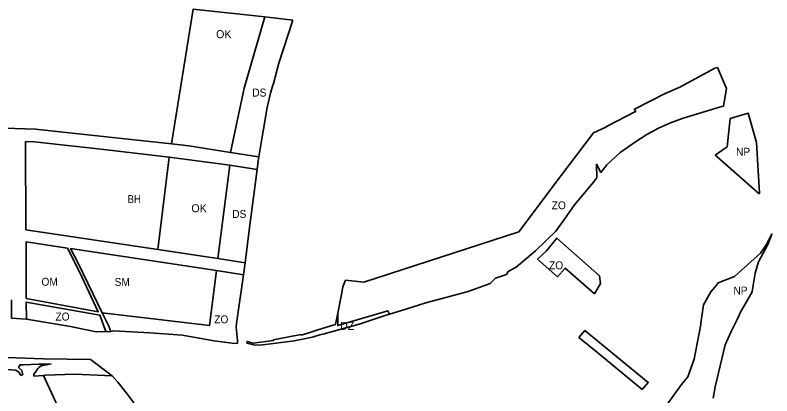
# Model space of a CAD drawing. Extents: x -650971 to -642489, y -1074311 to -1062745.
# Drawn here: x -647077 to -645942, y -1069933 to -1069362 of the extents above; entities that cross this region are included whole.
import ezdxf

# ---------------------------------------------------------------- set-up
doc = ezdxf.new("R2010")
doc.units = 0
doc.header["$LTSCALE"] = 4.8
for name, color, linetype, lineweight in [('1', 7, 'Continuous', 35), ('12', 7, 'Continuous', 35), ('13', 7, 'Continuous', 35), ('15', 7, 'Continuous', 35), ('18', 7, 'Continuous', 35), ('24', 7, 'Continuous', 35), ('25', 7, 'Continuous', 35), ('42', 7, 'Continuous', 35), ('48', 7, 'Continuous', 35), ('62', 7, 'Continuous', 35)]:
    doc.layers.add(name, color=color, linetype=linetype, lineweight=lineweight)

msp = doc.modelspace()

# ---------------------------------------------------------------- linework, layer by layer
at = {"layer": '1'}
msp.add_lwpolyline([(-646862.955, -1069713.633), (-647060.7, -1069683.894), (-647061.304, -1069551.773), (-647047.702, -1069552.239), (-646944.167, -1069563.743), (-646846, -1069575)], close=True, dxfattribs=at)
at = {"layer": '12'}
msp.add_lwpolyline([(-646998.56, -1069711.443), (-646980.4, -1069746.98), (-646952.56, -1069807.13), (-647060.23, -1069786.932), (-647060.617, -1069702.116)], close=True, dxfattribs=at)
at = {"layer": '13'}
for points in [[(-646842.441, -1069555.283), (-646809.879, -1069353.002), (-646702.425, -1069364.771)], [(-646702.425, -1069364.771), (-646733.74, -1069471.688), (-646754.066, -1069567.993)], [(-646754.066, -1069567.993), (-646816.615, -1069558.064), (-646842.441, -1069555.283)]]:
    msp.add_lwpolyline(points, dxfattribs=at)
msp.add_lwpolyline([(-646862.955, -1069713.633), (-646846, -1069575), (-646755.269, -1069587.04), (-646772.907, -1069727.176)], close=True, dxfattribs=at)
at = {"layer": '15'}
for points in [[(-647608.81, -1069551.868), (-647567.252, -1069548.083), (-647434.969, -1069537.141), (-647341.697, -1069532.602), (-647204.293, -1069530.647), (-647140.008, -1069530.068), (-647046.325, -1069533.275), (-646986.633, -1069539.757), (-646842.441, -1069555.283)], [(-646846, -1069575), (-646944.167, -1069563.743), (-647047.702, -1069552.239), (-647061.304, -1069551.773), (-647060.7, -1069683.894), (-646862.955, -1069713.633), (-646772.907, -1069727.176), (-646732.143, -1069733.308), (-646734.48, -1069751.35), (-646775.286, -1069745.022)], [(-646842.441, -1069555.283), (-646816.615, -1069558.064), (-646754.066, -1069567.993), (-646711.442, -1069574.759)], [(-646711.442, -1069574.759), (-646712.34, -1069580.49), (-646714.037, -1069593.585), (-646755.269, -1069587.04), (-646846, -1069575)], [(-646775.286, -1069745.022), (-646993.771, -1069712.163), (-646981.92, -1069734.86), (-646946.369, -1069808.291)], [(-647060.029, -1069817.854), (-647074.72, -1069816.8), (-647082.145, -1069816.321), (-647082.206, -1069802.916), (-647082.271, -1069788.81)], [(-646940.94, -1069836.34), (-646950.08, -1069812.16), (-647060.206, -1069792.294), (-647060.029, -1069817.854)], [(-646946.369, -1069808.291), (-646936.6, -1069828.47), (-646933.39, -1069836.51)], [(-646933.39, -1069836.51), (-646936.08, -1069837.11), (-646940.94, -1069836.34)], [(-646231.73, -1069845.42), (-646222.694, -1069834.722), (-646127.84, -1069912.695), (-646136.88, -1069923.39)], [(-646136.88, -1069923.39), (-646142.68, -1069918.62), (-646203.48, -1069868.65), (-646231.73, -1069845.42)], [(-647173.23, -1069871.09), (-647136.94, -1069872.55), (-647133.58, -1069872.73), (-647118.77, -1069873.51), (-647116.31, -1069873.65), (-647094.24, -1069874.85), (-647088.93, -1069875.14), (-647088.94, -1069875.34), (-647081.26, -1069875.76), (-647081.25, -1069875.56), (-647076, -1069875.85), (-647034.195, -1069877.629), (-646964.111, -1069878.315), (-646931.67, -1069902.89)], [(-647068.2, -1069902.28), (-647071, -1069897.87), (-647075.97, -1069894.33), (-647111.76, -1069891.77), (-647162.03, -1069888.89), (-647163.55, -1069887.98), (-647166.8, -1069885.63), (-647167.14, -1069884.85), (-647173.23, -1069871.09)], [(-647048.67, -1069903.32), (-647048.8, -1069900.51), (-647046.49, -1069897.19), (-647042.75, -1069892.14), (-647041.47, -1069890.42), (-647037.79, -1069887.88), (-647035.53, -1069887.44), (-647023.04, -1069885), (-647035.6, -1069885.43), (-647041.25, -1069885.62), (-647064.32, -1069886.23), (-647069.57, -1069886.35), (-647070.87, -1069888.71), (-647071.73, -1069890.39), (-647067.02, -1069894.68), (-647065.47, -1069901.09), (-647068.2, -1069902.28)], [(-646931.67, -1069902.89), (-646987.56, -1069900.52), (-647032.16, -1069902.13), (-647034.51, -1069902.21), (-647048.67, -1069903.32)]]:
    msp.add_lwpolyline(points, dxfattribs=at)
msp.add_lwpolyline([(-646998.56, -1069711.443), (-647060.617, -1069702.116), (-647060.23, -1069786.932), (-646952.56, -1069807.13), (-646980.4, -1069746.98)], close=True, dxfattribs=at)
at = {"layer": '18'}
for points in [[(-646946.369, -1069808.291), (-646981.92, -1069734.86), (-646993.771, -1069712.163), (-646775.286, -1069745.022)], [(-646775.286, -1069745.022), (-646785.437, -1069827.534), (-646946.369, -1069808.291)], [(-647043.25, -1070037.29), (-647021.27, -1070036.28), (-647024.05, -1069982.48), (-646998.06, -1069981.49), (-647034.51, -1069902.21)], [(-647034.51, -1069902.21), (-647032.16, -1069902.13), (-646987.56, -1069900.52), (-646931.67, -1069902.89)], [(-646931.67, -1069902.89), (-646922.79, -1069912.31), (-646909.48, -1069929.65), (-646900.26, -1069941.64), (-646894.42, -1069952.39), (-646886.85, -1069966.26), (-646857.06, -1070035.86), (-646855.62, -1070037.66), (-646849.79, -1070035.17), (-646849.33, -1070035.63), (-646837.65, -1070053.22), (-646816.9, -1070084.45), (-646817.15, -1070084.76)]]:
    msp.add_lwpolyline(points, dxfattribs=at)
at = {"layer": '24'}
for points in [[(-646754.066, -1069567.993), (-646733.74, -1069471.688), (-646702.425, -1069364.771), (-646660.526, -1069369.36)], [(-646660.526, -1069369.36), (-646681.5, -1069434.17), (-646689.8, -1069464.71), (-646690.51, -1069466.97), (-646694.26, -1069478.99), (-646699.07, -1069500.57), (-646704.68, -1069533.06), (-646707.16, -1069547.44), (-646711.442, -1069574.759), (-646754.066, -1069567.993)], [(-646772.907, -1069727.176), (-646755.269, -1069587.04), (-646714.037, -1069593.585)], [(-646714.037, -1069593.585), (-646725.82, -1069684.5), (-646732.143, -1069733.308), (-646772.907, -1069727.176)]]:
    msp.add_lwpolyline(points, dxfattribs=at)
at = {"layer": '25'}
for points in [[(-646515.63, -1069810.24), (-646522.32, -1069812.28), (-646560.92, -1069825.33), (-646613.65, -1069840.02), (-646620.06, -1069841.69), (-646629.83, -1069844.23), (-646635.93, -1069845.82), (-646658.5, -1069850.59), (-646689.73, -1069854.58), (-646705.87, -1069856.62), (-646717.66, -1069857.11), (-646729.54, -1069853.69)], [(-646723.5, -1069852.83), (-646719.82, -1069853.78), (-646689.63, -1069849.7), (-646689.8, -1069848.71), (-646664.22, -1069843.72), (-646648.18, -1069841.04), (-646648.28, -1069841.78), (-646638.34, -1069838.73), (-646623.31, -1069834.1), (-646599.9, -1069826.9), (-646596.7, -1069825.92), (-646593.34, -1069808.99)], [(-646593.34, -1069808.99), (-646593.34, -1069827.68), (-646518.19, -1069805.27), (-646515.63, -1069810.24)], [(-646729.54, -1069853.69), (-646729.24, -1069851.41), (-646723.5, -1069852.83)]]:
    msp.add_lwpolyline(points, dxfattribs=at)
at = {"layer": '42'}
for points in [[(-646189.17, -1069528.74), (-646146.8, -1069506.6), (-646148.5, -1069503), (-646102.15, -1069479.49), (-646080.35, -1069469.89), (-646028.16, -1069441.58), (-646023.96, -1069440.34), (-646010.65, -1069471.91)], [(-646010.65, -1069471.91), (-646015.16, -1069498.74), (-646017.63, -1069499.08)], [(-646017.63, -1069499.08), (-646020.75, -1069500), (-646075.48, -1069516.38), (-646094.39, -1069523.34), (-646112.56, -1069531.78), (-646129.87, -1069541.19), (-646146.81, -1069551.97), (-646169.9, -1069568.04), (-646190.07, -1069586.48), (-646198.82, -1069597.83), (-646205.25, -1069585.67), (-646205, -1069606.03), (-646205.9, -1069607.17), (-646210.03, -1069612.42), (-646212.43, -1069615.33), (-646238.19, -1069646.63), (-646250, -1069663.09), (-646266.27, -1069685.75), (-646296.64, -1069715.72), (-646325.92, -1069740.05), (-646337.97, -1069746.4), (-646340.48, -1069750.92), (-646357, -1069756.7), (-646364.67, -1069764.23), (-646397.74, -1069776.29), (-646460.97, -1069793.56), (-646491.18, -1069802.78), (-646515.63, -1069810.24)], [(-646258.086, -1069602.285), (-646209.9, -1069538.5), (-646191.4, -1069529.9), (-646189.17, -1069528.74)], [(-646581.489, -1069759.421), (-646554.262, -1069762.602), (-646321.973, -1069686.855), (-646258.086, -1069602.285)], [(-646293.76, -1069728), (-646280.5, -1069715.27), (-646265.02, -1069696.43), (-646200.67, -1069752.88)], [(-646208.135, -1069779.937), (-646252.07, -1069741.41), (-646263.929, -1069754.309), (-646293.76, -1069728)], [(-646946.369, -1069808.291), (-646785.437, -1069827.534), (-646775.286, -1069745.022), (-646734.48, -1069751.35)], [(-646734.48, -1069751.35), (-646744.309, -1069820.977), (-646745.38, -1069828.58), (-646745.56, -1069829.84), (-646743.7, -1069850.07), (-646743.31, -1069854.26)], [(-646200.67, -1069752.88), (-646199.17, -1069764.33), (-646204.6, -1069773.78), (-646208.135, -1069779.937)], [(-646593.34, -1069808.99), (-646588.25, -1069783.37), (-646585.51, -1069769.57), (-646581.489, -1069759.421)], [(-647060.029, -1069817.854), (-647060.206, -1069792.294), (-646950.08, -1069812.16), (-646940.94, -1069836.34)], [(-646933.39, -1069836.51), (-646936.6, -1069828.47), (-646946.369, -1069808.291)], [(-646515.63, -1069810.24), (-646518.19, -1069805.27), (-646593.34, -1069827.68), (-646593.34, -1069808.99)], [(-646940.94, -1069836.34), (-646955.45, -1069836.93), (-646993.81, -1069829.12), (-647060.029, -1069817.854)], [(-646743.31, -1069854.26), (-646751.8, -1069853.72), (-646778.74, -1069850.44), (-646826.63, -1069841.84), (-646853.88, -1069839.8), (-646875, -1069838.65), (-646929.67, -1069835.68), (-646933.39, -1069836.51)]]:
    msp.add_lwpolyline(points, dxfattribs=at)
at = {"layer": '48'}
for points in [[(-646027.49, -1069571.79), (-646017.39, -1069564.94), (-646009.52, -1069559.6), (-646004.7, -1069517.16)], [(-646004.7, -1069517.16), (-645977.73, -1069509.11), (-645965.36, -1069552.99), (-645960.78, -1069628.91), (-645961.36, -1069630.05)], [(-645961.36, -1069630.05), (-646020.4, -1069578.04), (-646027.49, -1069571.79)], [(-646104.04, -1069951.75), (-646077.78, -1069916.11), (-646068.5, -1069904.5), (-646058.71, -1069877.82), (-646049, -1069825.93), (-646048.71, -1069823.79), (-646044.94, -1069796.35), (-646034.02, -1069777.19), (-646025.11, -1069766.63), (-646022.72, -1069763.59), (-645998.57, -1069754.06), (-645993.22, -1069749.24), (-645959.63, -1069718.95), (-645951.52, -1069707.28), (-645942.41, -1069690.26), (-645948.22, -1069705.79), (-645962.48, -1069732.04), (-645967.35, -1069748.81), (-645968.78, -1069758.13), (-645971.7, -1069777.05), (-645983.89, -1069797.86), (-645989.01, -1069806.25), (-645993.96, -1069817.23), (-646003.18, -1069836.56), (-646012.37, -1069856.22), (-646027.3, -1069919.47), (-646030.62, -1069936.3)]]:
    msp.add_lwpolyline(points, dxfattribs=at)

# ---------------------------------------------------------------- texts
at = {"layer": '62'}
for s, p in [('OK', (-646775.694, -1069396.644)), ('OK', (-646812.694, -1069657.644)), ('DZ', (-646589.843, -1069833.949))]:
    msp.add_text(s, height=12, dxfattribs=at).set_placement(p)
for s, width, p in [('DS', 0.95, (-646721.423, -1069484.188)), ('NP', 0.95, (-645996.15, -1069572.972)), ('BH', 0.9, (-646908.386, -1069643.937)), ('ZO', 0.95, (-646272.423, -1069653.188)), ('DS', 0.95, (-646751.423, -1069666.188)), ('ZO', 0.95, (-646276.423, -1069743.188)), ('OM', 0.95, (-647037.483, -1069767.845)), ('SM', 0.95, (-646927.837, -1069768.153)), ('NP', 0.95, (-646000.15, -1069780.972)), ('ZO', 0.95, (-647016.473, -1069820.058)), ('ZO', 0.95, (-646778.423, -1069824.188))]:
    msp.add_text(s, height=12, dxfattribs=dict(at, width=width)).set_placement(p)

doc.saveas('drawing.dxf')
